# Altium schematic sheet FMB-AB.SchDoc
size A4
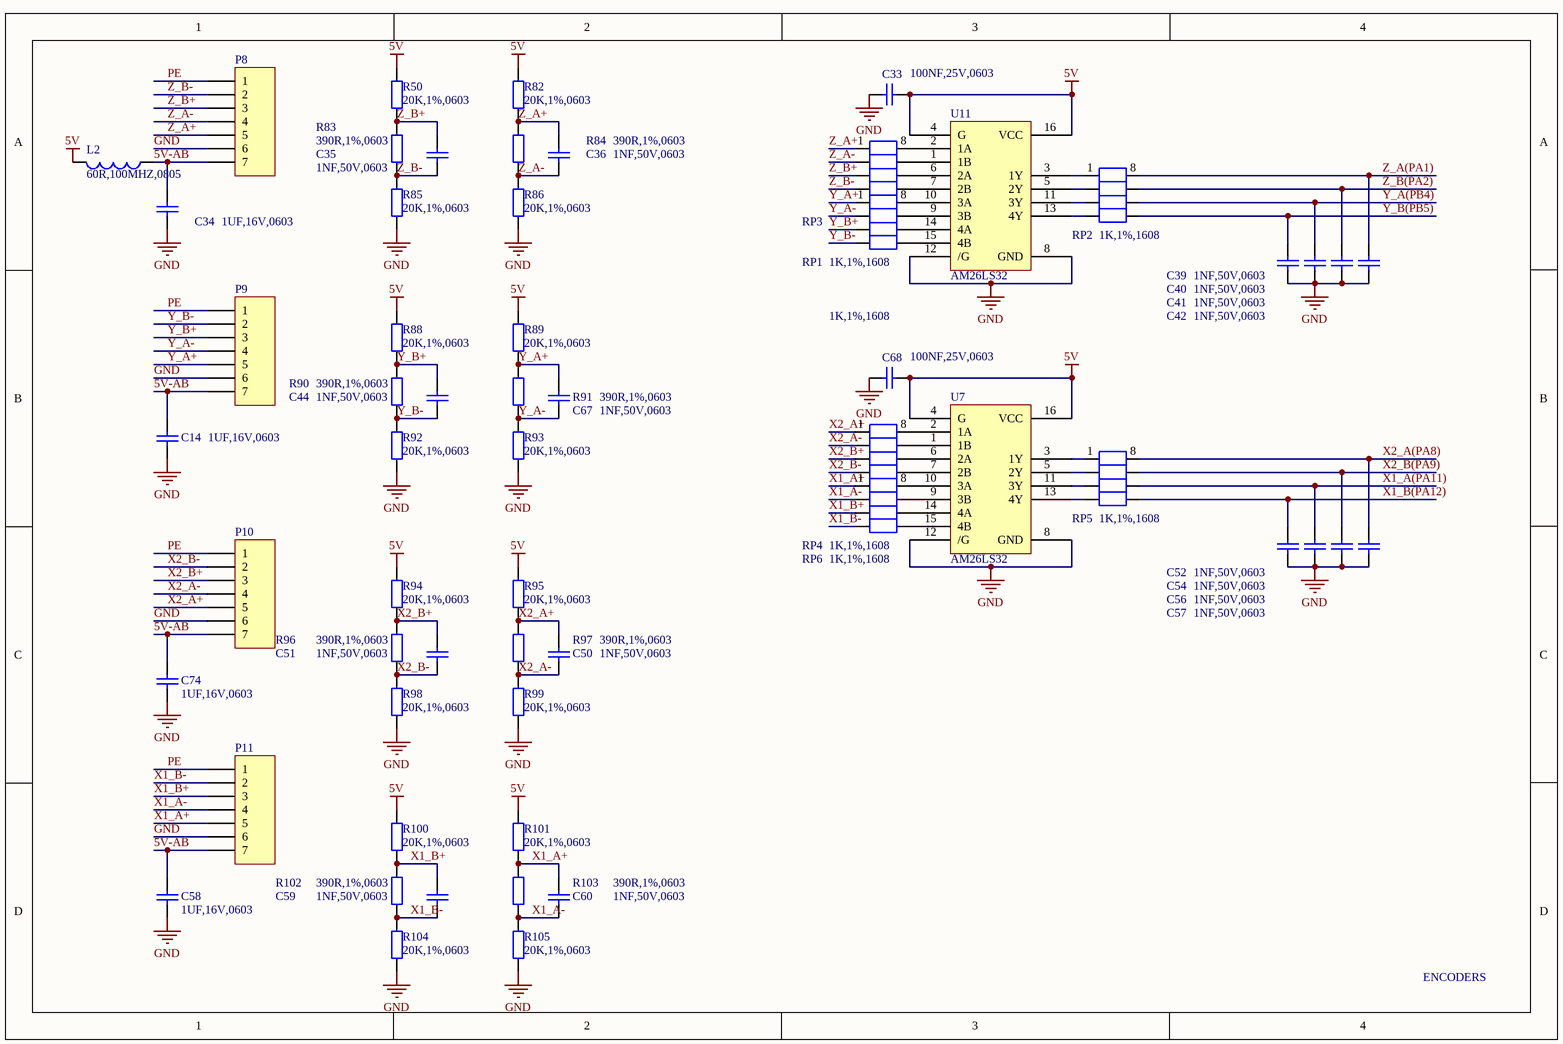
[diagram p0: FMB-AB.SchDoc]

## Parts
C14  1UF,16V,0603  [RC0603]
C33  100NF,25V,0603  [RC0603]
C34  1UF,16V,0603  [RC0603]
C35  1NF,50V,0603  [RC0603]
C36  1NF,50V,0603  [RC0603]
C39  1NF,50V,0603  [RC0603]
C40  1NF,50V,0603  [RC0603]
C41  1NF,50V,0603  [RC0603]
C42  1NF,50V,0603  [RC0603]
C44  1NF,50V,0603  [RC0603]
C50  1NF,50V,0603  [RC0603]
C51  1NF,50V,0603  [RC0603]
C52  1NF,50V,0603  [RC0603]
C54  1NF,50V,0603  [RC0603]
C56  1NF,50V,0603  [RC0603]
C57  1NF,50V,0603  [RC0603]
C58  1UF,16V,0603  [RC0603]
C59  1NF,50V,0603  [RC0603]
C60  1NF,50V,0603  [RC0603]
C67  1NF,50V,0603  [RC0603]
C68  100NF,25V,0603  [RC0603]
C74  1UF,16V,0603  [RC0603]
L2  60R,100MHZ,0805  [RC0805]
P8  Header 7  [DIP-1*7-2.54]  (value not drawn)
P9  Header 7  [DIP-1*7-2.54]  (value not drawn)
P10  Header 7  [DIP-1*7-2.54]  (value not drawn)
P11  Header 7  [DIP-1*7-2.54]  (value not drawn)
R50  20K,1%,0603  [RC0603]
R82  20K,1%,0603  [RC0603]
R83  390R,1%,0603  [RC0603]
R84  390R,1%,0603  [RC0603]
R85  20K,1%,0603  [RC0603]
R86  20K,1%,0603  [RC0603]
R88  20K,1%,0603  [RC0603]
R89  20K,1%,0603  [RC0603]
R90  390R,1%,0603  [RC0603]
R91  390R,1%,0603  [RC0603]
R92  20K,1%,0603  [RC0603]
R93  20K,1%,0603  [RC0603]
R94  20K,1%,0603  [RC0603]
R95  20K,1%,0603  [RC0603]
R96  390R,1%,0603  [RC0603]
R97  390R,1%,0603  [RC0603]
R98  20K,1%,0603  [RC0603]
R99  20K,1%,0603  [RC0603]
R100  20K,1%,0603  [RC0603]
R101  20K,1%,0603  [RC0603]
R102  390R,1%,0603  [RC0603]
R103  390R,1%,0603  [RC0603]
R104  20K,1%,0603  [RC0603]
R105  20K,1%,0603  [RC0603]
RP1  1K,1%,1608  [RP1608]
RP2  1K,1%,1608  [RP1608]
RP3  1K,1%,1608  [RP1608]
RP4  1K,1%,1608  [RP1608]
RP5  1K,1%,1608  [RP1608]
RP6  1K,1%,1608  [RP1608]
U7  AM26LS32  [SO-16-H]
U11  AM26LS32  [SO-16-H]

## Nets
5V: C33.1 C68.1 L2.2 R50.1 R82.1 R88.1 R89.1 R94.1 R95.1 R100.1 R101.1 U7.4(G) U7.16(VCC) U11.4(G) U11.16(VCC)
GND: C14.2 C33.2 C34.2 C39.1 C40.1 C41.1 C42.1 C52.1 C54.1 C56.1 C57.1 C58.2 C68.2 C74.2 P8.6 P9.6 P10.6 P11.6 R85.2 R86.2 R92.2 R93.2 R98.2 R99.2 R104.2 R105.2 U7.8(GND) U7.12(/G) U11.8(GND) U11.12(/G)
5V-AB: C14.1 C34.1 C58.1 C74.1 L2.1 P8.7 P9.7 P10.7 P11.7
PE: P8.1 P9.1 P10.1 P11.1
X1_A(PA11): C52.2 RP5.6
X1_A+: C60.2 P11.5 R101.2 R103.1 RP6.1
X1_A-: C60.1 P11.4 R103.2 R105.1 RP6.2
X1_B(PA12): C54.2 RP5.5
X1_B+: C59.2 P11.3 R100.2 R102.1 RP6.3
X1_B-: C59.1 P11.2 R102.2 R104.1 RP6.4
X2_A(PA8): C57.2 RP5.8
X2_A+: C50.2 P10.5 R95.2 R97.1 RP4.1
X2_A-: C50.1 P10.4 R97.2 R99.1 RP4.2
X2_B(PA9): C56.2 RP5.7
X2_B+: C51.2 P10.3 R94.2 R96.1 RP4.3
X2_B-: C51.1 P10.2 R96.2 R98.1 RP4.4
Y_A(PB4): C39.2 RP2.6
Y_A+: C67.2 P9.5 R89.2 R91.1 RP3.1
Y_A-: C67.1 P9.4 R91.2 R93.1 RP3.2
Y_B(PB5): C40.2 RP2.5
Y_B+: C44.2 P9.3 R88.2 R90.1 RP3.3
Y_B-: C44.1 P9.2 R90.2 R92.1 RP3.4
Z_A(PA1): C42.2 RP2.8
Z_A+: C36.2 P8.5 R82.2 R84.1 RP1.1
Z_A-: C36.1 P8.4 R84.2 R86.1 RP1.2
Z_B(PA2): C41.2 RP2.7
Z_B+: C35.2 P8.3 R50.2 R83.1 RP1.3
Z_B-: C35.1 P8.2 R83.2 R85.1 RP1.4
NetRP1_5: RP1.5 U11.7(2B)
NetRP1_6: RP1.6 U11.6(2A)
NetRP1_7: RP1.7 U11.1(1B)
NetRP1_8: RP1.8 U11.2(1A)
NetRP2_1: RP2.1 U11.3(1Y)
NetRP2_2: RP2.2 U11.5(2Y)
NetRP2_3: RP2.3 U11.11(3Y)
NetRP2_4: RP2.4 U11.13(4Y)
NetRP3_5: RP3.5 U11.15(4B)
NetRP3_6: RP3.6 U11.14(4A)
NetRP3_7: RP3.7 U11.9(3B)
NetRP3_8: RP3.8 U11.10(3A)
NetRP4_5: RP4.5 U7.7(2B)
NetRP4_6: RP4.6 U7.6(2A)
NetRP4_7: RP4.7 U7.1(1B)
NetRP4_8: RP4.8 U7.2(1A)
NetRP5_1: RP5.1 U7.3(1Y)
NetRP5_2: RP5.2 U7.5(2Y)
NetRP5_3: RP5.3 U7.11(3Y)
NetRP5_4: RP5.4 U7.13(4Y)
NetRP6_5: RP6.5 U7.15(4B)
NetRP6_6: RP6.6 U7.14(4A)
NetRP6_7: RP6.7 U7.9(3B)
NetRP6_8: RP6.8 U7.10(3A)

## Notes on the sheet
- ENCODERS

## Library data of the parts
C14 C33-C36 C39-C42 C44 C50-C52 C54 C56-C60 C67 C68 C74 = Cap: Capacitor; Value: 100pF
L2 = Inductor: Code_IEC: 1005; Value: 10mH
P8-P11 = Header 7: Header, 7-Pin
R50 R82-R86 R88-R105 = Res2: Resistor; Value: 1K
RP1-RP6 = RP1608-1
